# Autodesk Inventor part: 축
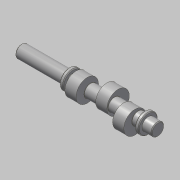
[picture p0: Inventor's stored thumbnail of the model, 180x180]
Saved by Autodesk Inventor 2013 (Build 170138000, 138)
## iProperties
Company: 한국ATC센터
Created: 2014-08
Part Number: 축
Document SubType Name: Modeling
Designer: mdu
Density: 7.86 g/cm^3
Material: 강철, 연강
Mass: 516.584 g
Surface Area: 162.515 cm^2
Volume: 65.7231 cm^3
Author: mdu
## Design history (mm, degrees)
sketch "스케치1"
  geometry: L1 (-91.5, 0)-(91.5, 0); L2 (-91.5, 0)-(-91.5, 8.5); L3 (-91.5, 8.5)-(-27.5, 8.5); L4 (-27.5, 8.5)-(-27.5, 13); L5 (-27.5, 13)-(-22.5, 13); L6 (-22.5, 13)-(-22.5, 8.5); L7 (-22.5, 8.5)-(73.5, 8.5); L8 (73.5, 8.5)-(73.5, 13); L9 (73.5, 13)-(78.5, 13); L10 (78.5, 13)-(78.5, 8.5); L11 (78.5, 8.5)-(91.5, 8.5); L12 (91.5, 8.5)-(91.5, 0); 2 further points
  constraints: 24 end point, 5 parallel, 1 coincident, 1 horizontal, 1 midpoint, 1 perpendicular
  dimensions: "d0" = 183 distance of L1.start L1.end (derived); "d2" = 17 diameter of L3 L1; "d3" = 26 diameter of L5 L1; "d4" = 17 diameter of L7 L1; "d5" = 26 diameter of L9 L1; "d6" = 17 diameter of L11 L1; "d7" = 5 distance of L8.end L9.end; "d8" = 5 distance of L4.end L5.end; "d10" = 64 distance of L2.end L3.end; "d11" = 13 distance of L10.end L11.end; "d35" = 96 distance between parallel lines of L8 L6
revolve "회전1" sketch "스케치1" stored, may be unused: angle "d12" = 90 deg
node "작업 평면7"
sketch "스케치6"
  geometry: C1 r 15 at (0, 5); 1 further point
  constraints: 1 centre point, 1 vertical alignment
  dimensions: "d37" = 30 diameter of C1; "d38" = 5 distance of C1.centre point (0, 0)
extrude "돌출4" join sketch "스케치6" stored distance "d33" = 15; taper "d34" = 0 deg
node "작업 평면8"
sketch "스케치7"
  geometry: L1 (0, 0)-(-6.5, -11.258); L2 (0, 0)-(13, 0); C1 r 15 at (-2.5, -4.33); A1 r 13 centre (0, 0) between (-6.5, -11.258) and (13, 0) reference; 1 further point
  constraints: 4 end point, 2 point on circle, 1 centre point, 1 horizontal, 1 point on line
  dimensions: "d40" = 120 deg angle of L1 L2; "d41" = 30 diameter of C1; "d42" = 5 distance of point (0, 0) C1.centre
extrude "돌출5" join sketch "스케치7" stored distance "d43" = 15; taper "d44" = 0 deg
node "작업 평면9"
sketch "스케치8"
  geometry: L1 (0, 0)-(4.25, -7.361); L2 (0, 0)-(-8.5, 0); C1 r 15 at (2.5, -4.33); A1 r 8.5 centre (0, 0) between (4.25, -7.361) and (-8.5, 0) reference; 1 further point
  constraints: 4 end point, 2 point on circle, 1 centre point, 1 horizontal, 1 point on line
  dimensions: "d46" = 120 deg angle of L1 L2; "d47" = 30 diameter of C1; "d48" = 5 distance of point (0, 0) C1.centre
extrude "돌출6" join sketch "스케치8" stored distance "d49" = 15; taper "d50" = 0 deg
node "작업 평면3"
sketch "스케치5"
  geometry: L1 (32, 8.5)-(32, -8.5) reference; L2 (27.5, -2.5)-(14.5, -2.5); L3 (14.5, 2.5)-(27.5, 2.5); A1 r 2.5 centre (14.5, 0) between (14.5, 2.5) and (14.5, -2.5); A2 r 2.5 centre (27.5, 0) between (27.5, -2.5) and (27.5, 2.5); 4 further points
  constraints: 4 end point, 4 point on circle, 4 tangent, 2 centre point, 2 point on line, 1 horizontal alignment, 1 midpoint, 1 parallel, 1 perpendicular
  dimensions: "d23" = 5 distance between parallel lines of L3 L2; "d36" = 20 dimension on A1 L1; "d52" = 2 distance edge to line of A2 L1
extrude "돌출3" cut sketch "스케치5" distance "d25" = 3; taper "d26" = 0 deg
chamfer "모따기1" distance "d27" = 1; stored, may be unused: second distance "d28" = 2, angle "d29" = 45 deg
fillet "모깎기1" dims "d51" = 0.3
chamfer "모따기2" distance "d53" = 1; stored, may be unused: second distance "d54" = 2, angle "d55" = 45 deg
node "작업 평면10"
node "솔리드1"
other parameters: "d39" = -32, "d45" = 32
